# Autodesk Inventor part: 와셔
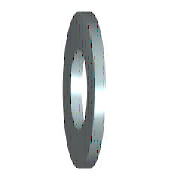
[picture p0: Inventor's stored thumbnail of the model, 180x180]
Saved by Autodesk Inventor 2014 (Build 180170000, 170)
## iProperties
IsCustomPart: 1
Created: 2012-02
Part Number: 와셔
Material: 강철, 연강
Description: 평면 와셔
Document SubType Name: Modeling
Standard: KS B 1326
Designer: mduedu
Standards Organization: KS
Language: ko-KR
Size Designation: 8x15.5
Categories: <MemberInstance><Categories><Category DisplayName="조임쇠" InternalName="e4da775c-781d-43d5-af7c-5136215cf5a6" Mnemonic="FSTN"><Category DisplayName="와셔" InternalN
Density: 1 g/cm^3
Appearance: Orange
Author: mduedu
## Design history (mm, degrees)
sketch "스케치"
  geometry: C1 r 7.75 at (0, 0); C2 r 4.2 at (0, 0); 1 further point
  constraints: 2 centre point, 2 coincident
  dimensions: "d0" = 8.4 diameter of C2 (= SD1); "d1" = 15.5 diameter of C1 (= SD2)
extrude "본체" new body sketch "스케치" distance "d2" = 1.6 (= SD); taper "d3" = 0 deg
workaxis "Work Axis1"
workplane "Work Plane1"
body "Solid1"
other parameters: "SD1" = 8.4 [user parameter; used in 1 equation term], "SD2" = 15.5 [user parameter; used in 1 equation term], "SD" = 1.6 [user parameter; used in 1 equation term], "d4" = 0, "d5" = 0, "d6" = 0, "d7" = 0, "NND" = 8 [user parameter]
